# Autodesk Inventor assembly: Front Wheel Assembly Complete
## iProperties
Length Units: 11269
Angle Units: 11279
Time Units: 11290
Mass Units: 11283
Shininess: 3
Angle Display Precision: 2
Document Length Units: 11269
Document Angle Units: 11279
Document Time Units: 11290
Document Mass Units: 11283
Document Length Units Precision: 3
Document Angle Units Precision: 2
Compacted: True
Created: 2001-08
Part Number: Front Wheel Assembly Complete
Document SubType Name: Assembly
Designer: Martin Budgell
Density: 0.0
Volumn: 0.0
Area: 0.0
PropertySet Name: Model Information
Control State: 0
Master: False
Checked Out: False
Author: Martin Budgell
